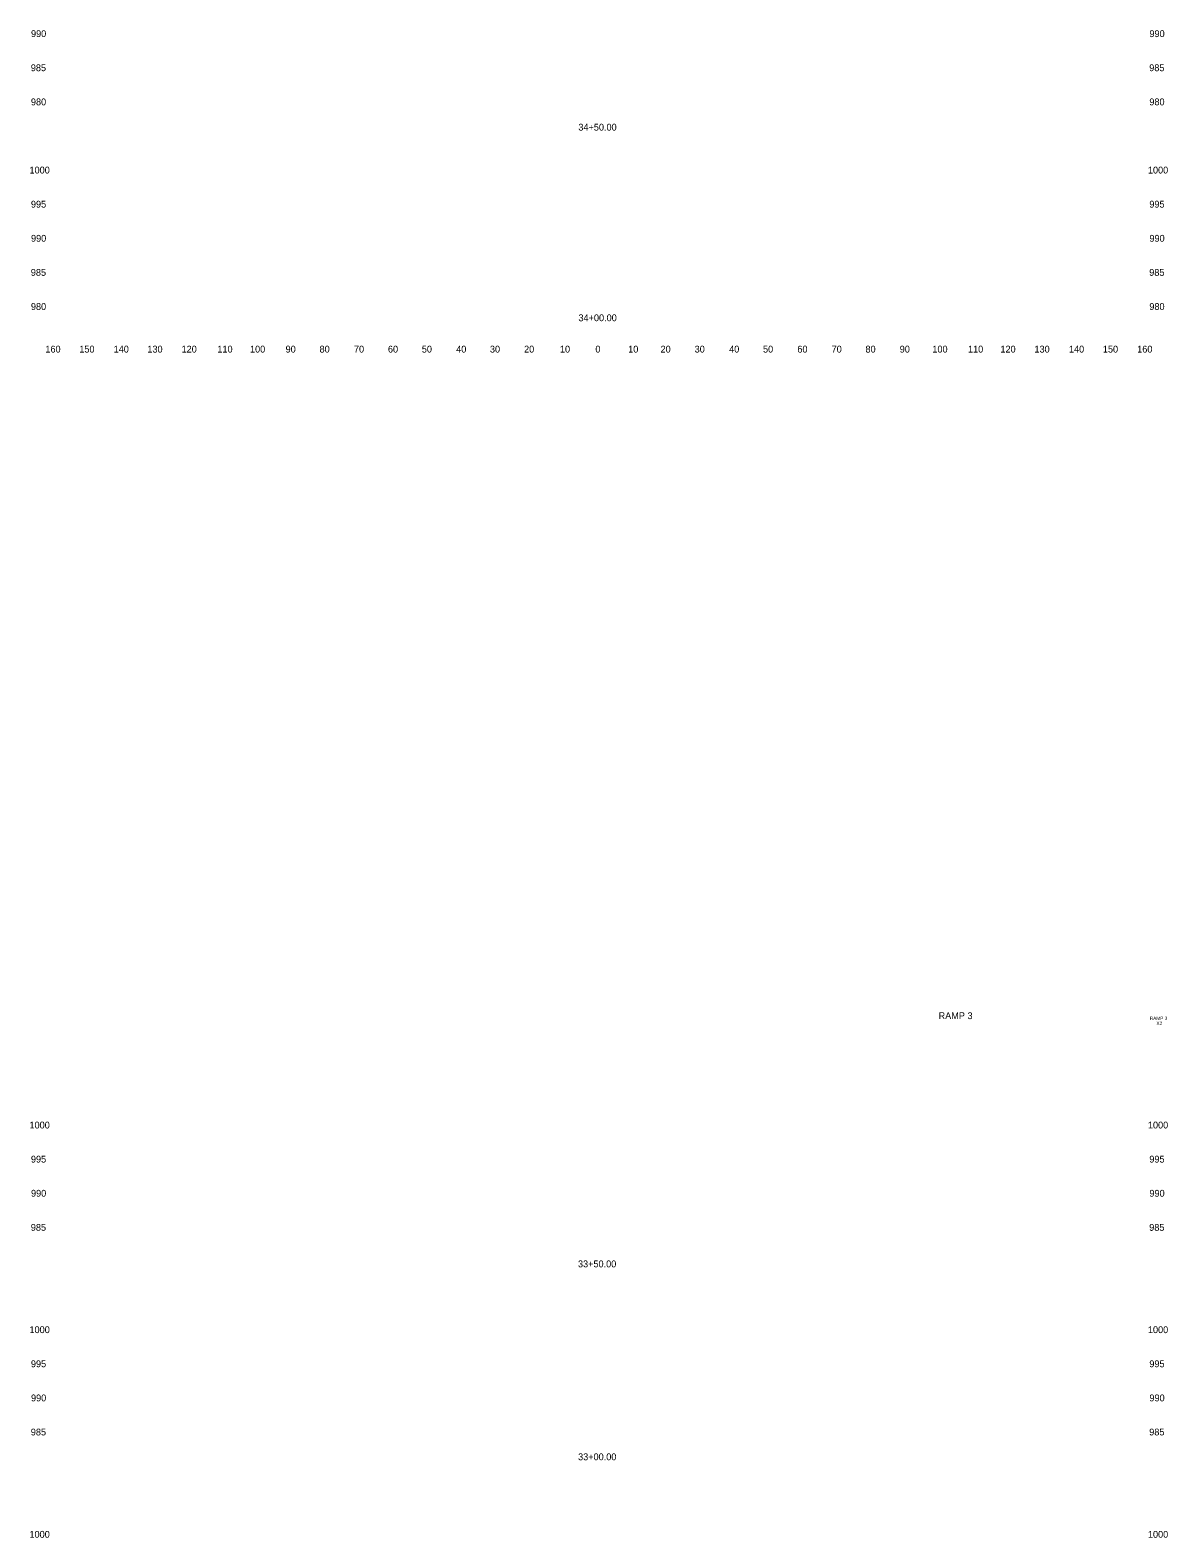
# Model space of a CAD drawing. Extents: x 4994 to 5843, y 4997 to 8804.
# Drawn here: x 4993.6 to 5327.1, y 5450 to 5892 of the extents above; entities that cross this region are included whole.
import ezdxf

# ---------------------------------------------------------------- set-up
doc = ezdxf.new("R2010")
doc.units = 0
for name, color, linetype in [('RD_SHT_ID', 7, 'Continuous'), ('RD_XS_TX_Offset', 7, 'Continuous'), ('RD_XS_TX_Station', 7, 'Continuous')]:
    doc.layers.add(name, color=color, linetype=linetype)

msp = doc.modelspace()

# ---------------------------------------------------------------- texts
at = {"layer": 'RD_SHT_ID'}
for s, height, p in [('RAMP 3', 2, (5259.89, 5602.06)), ('RAMP 3', 1, (5321.78, 5601.8)), ('X2', 1, (5323.74, 5600.3))]:
    msp.add_text(s, height=height, dxfattribs=at).set_placement(p)
at = {"layer": 'RD_XS_TX_Offset'}
for s, p in [('990', (4993.89, 5890)), ('990', (5321.69, 5890)), ('985', (4993.83, 5880)), ('985', (5321.63, 5880)), ('980', (4993.86, 5870)), ('980', (5321.66, 5870)), ('1000', (4993.44, 5850)), ('1000', (5321.24, 5850)), ('995', (4993.86, 5840)), ('995', (5321.66, 5840)), ('990', (4993.89, 5830)), ('990', (5321.69, 5830)), ('985', (4993.83, 5820)), ('985', (5321.63, 5820)), ('980', (4993.86, 5810)), ('980', (5321.66, 5810)), ('160', (4998.1, 5797.5)), ('150', (5008.04, 5797.5)), ('140', (5018.1, 5797.5)), ('130', (5027.99, 5797.5)), ('120', (5038.01, 5797.5)), ('110', (5048.51, 5797.5)), ('100', (5058.07, 5797.5)), ('90', (5068.5, 5797.5)), ('80', (5078.46, 5797.5)), ('70', (5088.54, 5797.5)), ('60', (5098.5, 5797.5)), ('50', (5108.43, 5797.5)), ('40', (5118.5, 5797.5)), ('30', (5128.39, 5797.5)), ('20', (5138.4, 5797.5)), ('10', (5148.91, 5797.5)), ('0', (5159.3, 5797.5)), ('0', (5159.3, 5797.5)), ('10', (5168.91, 5797.5)), ('20', (5178.4, 5797.5)), ('30', (5188.39, 5797.5)), ('40', (5198.5, 5797.5)), ('50', (5208.43, 5797.5)), ('60', (5218.5, 5797.5)), ('70', (5228.54, 5797.5)), ('80', (5238.46, 5797.5)), ('90', (5248.5, 5797.5)), ('100', (5258.07, 5797.5)), ('110', (5268.51, 5797.5)), ('120', (5278.01, 5797.5)), ('130', (5287.99, 5797.5)), ('140', (5298.1, 5797.5)), ('150', (5308.04, 5797.5)), ('160', (5318.1, 5797.5)), ('1000', (4993.44, 5570)), ('1000', (5321.24, 5570)), ('995', (4993.86, 5560)), ('995', (5321.66, 5560)), ('990', (4993.89, 5550)), ('990', (5321.69, 5550)), ('985', (4993.83, 5540)), ('985', (5321.63, 5540)), ('1000', (4993.44, 5510)), ('1000', (5321.24, 5510)), ('995', (4993.86, 5500)), ('995', (5321.66, 5500)), ('990', (4993.89, 5490)), ('990', (5321.69, 5490)), ('985', (4993.83, 5480)), ('985', (5321.63, 5480)), ('1000', (4993.44, 5450)), ('1000', (5321.24, 5450))]:
    msp.add_text(s, height=2, dxfattribs=at).set_placement(p)
at = {"layer": 'RD_XS_TX_Station'}
for s, p in [('34+50.00', (5154.31, 5862.58)), ('34+00.00', (5154.34, 5806.69)), ('33+50.00', (5154.2, 5529.3)), ('33+00.00', (5154.23, 5472.73))]:
    msp.add_text(s, height=2, dxfattribs=at).set_placement(p)

doc.saveas('drawing.dxf')
